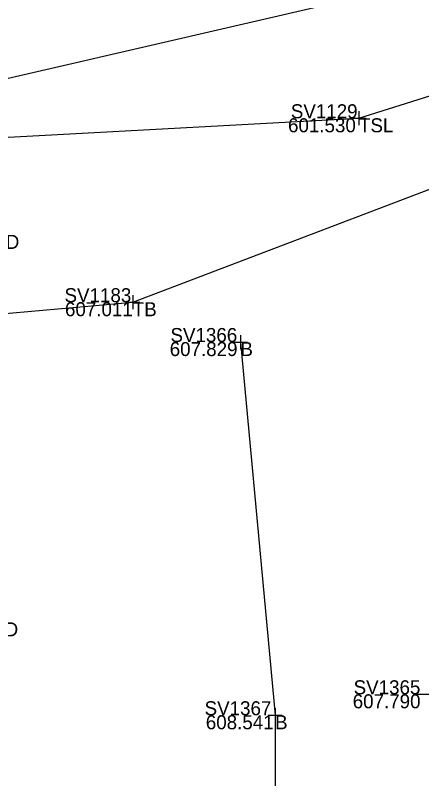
# Model space of a CAD drawing. Extents: x -2 to 1979875, y -2 to 232027.
# Drawn here: x 1978804.84 to 1978819.33, y 231234.17 to 231261.41 of the extents above; entities that cross this region are included whole.
import ezdxf

# ---------------------------------------------------------------- set-up
doc = ezdxf.new("R2010")
doc.units = 0
for name, color, linetype in [('_CIVIL_CONSTRUCTION', 7, 'Continuous'), ('DR_X_Ditch', 7, 'Continuous'), ('GE_P_Alignment', 7, 'Continuous'), ('GE_X_Alignment', 7, 'Continuous'), ('GE_X_Alignment_100_Curve_Data', 7, 'Continuous'), ('GE_X_Alignment_100_Stations', 7, 'Continuous'), ('HY_X_Water_Edge', 7, 'Continuous'), ('SV_X_Toe_of_Slope', 7, 'Continuous'), ('SV_X_Top_of_Bank', 7, 'Continuous')]:
    doc.layers.add(name, color=color, linetype=linetype)

msp = doc.modelspace()

# ---------------------------------------------------------------- linework, layer by layer
at = {"layer": 'DR_X_Ditch'}
msp.add_lwpolyline([(1978888.584, 231299.627), (1978879.993, 231287.447), (1978870.172, 231277.213), (1978856.534, 231274.917), (1978839.012, 231271.025), (1978823.007, 231263.425), (1978802.617, 231258.705), (1978787.259, 231269.564)], dxfattribs=at)
at = {"layer": 'GE_P_Alignment'}
msp.add_lwpolyline([(1978812.863, 231249.753), (1978814.099, 231236.437), (1978814.107, 231225.285), (1978812.479, 231213.477)], dxfattribs=at)
at = {"layer": 'GE_X_Alignment_100_Curve_Data'}
for p, q in [((1978817.09, 231257.987), (1978817.09, 231257.487)), ((1978816.84, 231257.737), (1978817.34, 231257.737)), ((1978817.09, 231257.737), (1978817.09, 231257.737)), ((1978809.026, 231251.424), (1978809.026, 231250.924)), ((1978808.776, 231251.174), (1978809.276, 231251.174)), ((1978809.026, 231251.174), (1978809.026, 231251.174)), ((1978812.863, 231250.003), (1978812.863, 231249.503)), ((1978812.613, 231249.753), (1978813.113, 231249.753)), ((1978812.863, 231249.753), (1978812.863, 231249.753)), ((1978819.146, 231237.185), (1978819.646, 231237.185)), ((1978814.099, 231236.687), (1978814.099, 231236.187)), ((1978813.849, 231236.437), (1978814.349, 231236.437)), ((1978814.099, 231236.437), (1978814.099, 231236.437))]:
    msp.add_line(p, q, dxfattribs=at)
at = {"layer": 'HY_X_Water_Edge'}
msp.add_lwpolyline([(1978710.396, 231262.363), (1978725.371, 231260.246), (1978739.363, 231256.715), (1978742.039, 231254.081), (1978754.512, 231255.046), (1978783.289, 231254.287), (1978787.737, 231256.586), (1978799.967, 231256.811), (1978817.09, 231257.737), (1978832.082, 231262.479)], dxfattribs=at)
at = {"layer": 'SV_X_Toe_of_Slope'}
msp.add_lwpolyline([(1978783.289, 231254.287), (1978787.737, 231256.586), (1978799.967, 231256.811), (1978817.09, 231257.737), (1978832.082, 231262.479), (1978831.856, 231267.326), (1978861.367, 231270.387), (1978875.304, 231272.806), (1978884.386, 231282.392), (1978891.721, 231292.42), (1978902.966, 231322.566)], dxfattribs=at)
at = {"layer": 'SV_X_Top_of_Bank'}
msp.add_lwpolyline([(1978792.729, 231249.351), (1978802.059, 231250.56), (1978809.026, 231251.174), (1978824.702, 231257.152), (1978834.668, 231262.265), (1978843.76, 231264.082), (1978857.569, 231267.988), (1978870.834, 231267.898), (1978882.845, 231275.772), (1978894.192, 231280.826), (1978903.719, 231297.628)], dxfattribs=at)

# ---------------------------------------------------------------- texts
at = {"layer": '_CIVIL_CONSTRUCTION'}
for s, p in [('601.530', (1978814.56, 231257.237)), ('607.011', (1978806.608, 231250.674)), ('607.829', (1978810.342, 231249.253)), ('607.790', (1978816.866, 231236.685)), ('608.541', (1978811.629, 231235.937))]:
    msp.add_text(s, height=0.5, dxfattribs=at).set_placement(p)
at = {"layer": 'GE_X_Alignment'}
for s, p in [('SV1129', (1978814.66, 231257.737)), ('SV1183', (1978806.592, 231251.174)), ('SV1366', (1978810.369, 231249.753)), ('SV1365', (1978816.899, 231237.185)), ('SV1367', (1978811.586, 231236.437))]:
    msp.add_text(s, height=0.5, dxfattribs=at).set_placement(p)
at = {"layer": 'GE_X_Alignment_100_Stations'}
for s, p in [('TSL', (1978817.09, 231257.237)), ('D', (1978804.498, 231253.077)), ('TB', (1978809.026, 231250.674)), ('B', (1978812.863, 231249.253)), ('D', (1978804.457, 231239.252)), ('B', (1978814.099, 231235.937))]:
    msp.add_text(s, height=0.5, dxfattribs=at).set_placement(p)

doc.saveas('drawing.dxf')
